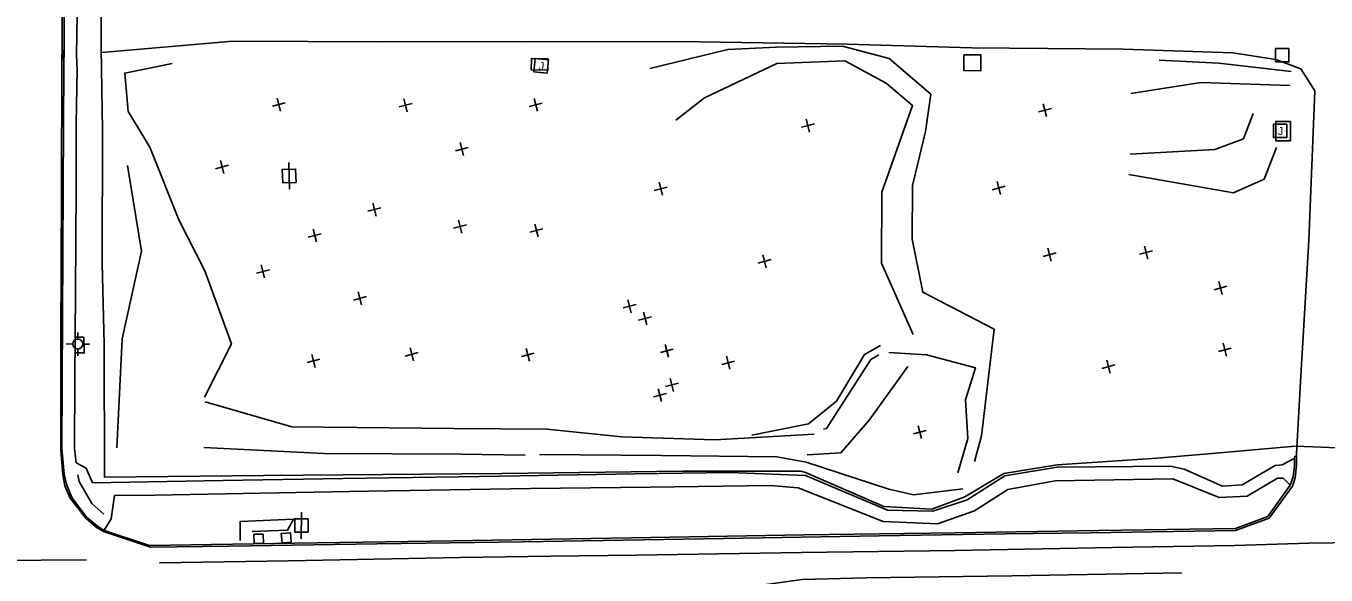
# Model space of a CAD drawing. Extents: x 4711259 to 4716401, y 890074 to 892728.
# Drawn here: x 4712099.3 to 4712586.5, y 891365.1 to 891570.9 of the extents above; entities that cross this region are included whole.
import ezdxf

# ---------------------------------------------------------------- set-up
doc = ezdxf.new("R2010")
doc.units = 0
for name, color, linetype in [('E_HY_STORM_Inlet', 7, 'Continuous'), ('E_RDWY_PHOTOG_Fence', 7, 'Continuous'), ('E_RDWY_ROAD_Curb', 7, 'Continuous'), ('E_RDWY_ROAD_EdgeAsph', 7, 'Continuous'), ('E_RDWY_ROAD_EdgeConc', 7, 'Continuous'), ('E_RDWY_ROAD_Fence', 7, 'Continuous'), ('E_RDWY_ROAD_Sidewalk', 7, 'Continuous'), ('E_RDWY_ROAD_Striping', 7, 'Continuous'), ('E_RDWY_ROAD_TBofCurb', 7, 'Continuous'), ('E_TERR_DTM_BrkLines', 7, 'Continuous'), ('E_TERR_DTM_RandomPt', 7, 'Continuous'), ('E_UTIL_COMM_General', 7, 'Continuous'), ('E_UTIL_ELEC_GENERAL', 7, 'Continuous'), ('E_UTIL_ELEC_POLE', 7, 'Continuous'), ('E_UTIL_WTR_General', 7, 'Continuous')]:
    doc.layers.add(name, color=color, linetype=linetype)

msp = doc.modelspace()

# ---------------------------------------------------------------- linework, layer by layer
at = {"layer": 'E_HY_STORM_Inlet'}
msp.add_line((4712570.08, 891559.94), (4712570.08, 891559.94), dxfattribs=at)
msp.add_lwpolyline([(4712572.6, 891562.42), (4712572.56, 891557.42), (4712567.56, 891557.46), (4712567.6, 891562.46)], close=True, dxfattribs=at)
at = {"layer": 'E_RDWY_PHOTOG_Fence'}
for points in [[(4712574.97, 891413.38), (4712548.05, 891411.03), (4712523.15, 891408.85)], [(4712597.22, 891412.51), (4712575.15, 891413.33)], [(4712389.68, 891403.96), (4712391.41, 891403.56), (4712420.78, 891390.76), (4712438.69, 891389.77), (4712451.16, 891394.32), (4712465.69, 891403.09), (4712485.68, 891406.34), (4712523.15, 891408.85)], [(4712389.68, 891403.96), (4712345.41, 891403.96), (4712277.64, 891403.09)]]:
    msp.add_lwpolyline(points, dxfattribs=at)
at = {"layer": 'E_RDWY_ROAD_Curb'}
for points in [[(4712128.26, 891381.39), (4712125.55, 891383.03), (4712121.64, 891386.33), (4712115.83, 891393.82), (4712113.87, 891398.54), (4712113.04, 891402.77), (4712112.33, 891411.88), (4712112.37, 891453.3), (4712112.58, 891509.08), (4712112.73, 891556.54), (4712112.81, 891563.66), (4712113, 891591.26), (4712112.87, 891594.89), (4712113.25, 891611.03), (4712113.37, 891640.66), (4712113.52, 891682.17), (4712113.29, 891731.86), (4712112.03, 891796.52), (4712110.46, 891860.01), (4712109.29, 891889.41), (4712108.95, 891893.59), (4712107.64, 891922.46)], [(4712575.38, 891410.55), (4712575.36, 891406.08), (4712574.89, 891401.56), (4712573.93, 891398.33), (4712565.14, 891386.35), (4712552.59, 891381.81), (4712498.06, 891380.95), (4712466.16, 891380.48), (4712418.96, 891379.75), (4712360.71, 891378.82), (4712285.61, 891377.51)], [(4712145.91, 891375.46), (4712128.26, 891381.39)], [(4712285.61, 891377.51), (4712230.79, 891376.79), (4712175.47, 891375.85), (4712145.91, 891375.46)]]:
    msp.add_lwpolyline(points, dxfattribs=at)
at = {"layer": 'E_RDWY_ROAD_EdgeAsph'}
for points in [[(4712286.19, 891565.02), (4712233.05, 891564.94), (4712176.76, 891565.2), (4712127.72, 891560.88)], [(4712286.19, 891565.02), (4712351.62, 891564.91), (4712406.96, 891564.03), (4712453.7, 891562.63), (4712510.49, 891562.11), (4712551.53, 891560.76), (4712567.71, 891558.31), (4712577.04, 891554.83), (4712582.3, 891546.57)], [(4712582.3, 891546.57), (4712579.98, 891490.4), (4712576.93, 891437.62), (4712575.38, 891410.55)]]:
    msp.add_lwpolyline(points, dxfattribs=at)
at = {"layer": 'E_RDWY_ROAD_EdgeConc'}
for points in [[(4712288.57, 891554.45), (4712288.71, 891558.7), (4712294.97, 891558.51), (4712294.84, 891554.26)], [(4712450.79, 891560.05), (4712457.14, 891560.04), (4712457.12, 891554.11), (4712450.77, 891554.12)], [(4712573.14, 891535.11), (4712573.15, 891527.86), (4712567.65, 891527.85), (4712567.63, 891535.1)]]:
    msp.add_lwpolyline(points, close=True, dxfattribs=at)
msp.add_lwpolyline([(4712118.08, 891448.31), (4712121.08, 891448.31), (4712120.93, 891454.19), (4712117.99, 891454.18)], dxfattribs=at)
at = {"layer": 'E_RDWY_ROAD_Fence'}
for points in [[(4712128.59, 891451.64), (4712127.77, 891481.95), (4712127.92, 891531.97), (4712127.41, 891562.39), (4712127.6, 891590.09), (4712127.3, 891649.86), (4712127.17, 891700.22), (4712128.2, 891710.35), (4712134.44, 891739.35), (4712132.91, 891765.97), (4712132.02, 891783.01), (4712129.51, 891829.8), (4712126.66, 891879.73), (4712124.56, 891919.3), (4712121.22, 891968.8), (4712118.38, 892019.02), (4712115.97, 892060.36), (4712113.52, 892109.62), (4712110.82, 892170.44), (4712108.89, 892208.75)], [(4712277.64, 891403.09), (4712188.43, 891402.32), (4712128.73, 891401.7), (4712128.59, 891451.64)]]:
    msp.add_lwpolyline(points, dxfattribs=at)
at = {"layer": 'E_RDWY_ROAD_Sidewalk'}
for points in [[(4712118.88, 891695.33), (4712118.95, 891660.37), (4712118.95, 891642.42), (4712123.96, 891628.2), (4712124.58, 891622.91), (4712123, 891617.48), (4712118.71, 891609.04), (4712118.53, 891594.89), (4712118.62, 891582.72), (4712118.2, 891560.08), (4712118.39, 891554.48), (4712118.03, 891534.35), (4712118.11, 891510.21), (4712117.8, 891471.09), (4712117.51, 891438.4), (4712117.47, 891412.49), (4712118.02, 891407.07)], [(4712118.02, 891407.07), (4712121.82, 891405.17), (4712124.23, 891399.67), (4712173.07, 891400.45), (4712218.17, 891401.25), (4712261.66, 891401.93), (4712284.19, 891402.25)], [(4712574.55, 891408.71), (4712570, 891406.34), (4712567.41, 891406.14), (4712555.06, 891398.93), (4712547.65, 891398.38), (4712533.37, 891404.8), (4712528.25, 891405.86), (4712485.78, 891405.47), (4712466.11, 891402.28), (4712451.99, 891393.22), (4712439.16, 891388.96), (4712422.12, 891389.43), (4712391.37, 891402.4), (4712363.15, 891403.48), (4712327.47, 891402.99), (4712284.19, 891402.25)], [(4712288.4, 891397.56), (4712220.44, 891396.41), (4712147.6, 891395.04), (4712132.46, 891394.86), (4712131.14, 891386.08), (4712128.62, 891381.88)], [(4712288.4, 891397.56), (4712333.35, 891397.98), (4712378.33, 891398.62), (4712388.68, 891397.76), (4712420.57, 891385.13), (4712440.82, 891384.21), (4712454.68, 891389.17), (4712467.23, 891397.19), (4712484.91, 891400.37), (4712529.06, 891401.07), (4712546.47, 891394.15), (4712556.93, 891394.63), (4712568.28, 891401.32), (4712570.38, 891401.35), (4712573.08, 891398.72)]]:
    msp.add_lwpolyline(points, dxfattribs=at)
at = {"layer": 'E_RDWY_ROAD_Striping'}
for points in [[(4712295.9, 891372.09), (4712327.97, 891372.54), (4712389.88, 891373.54), (4712447.54, 891374.26), (4712506.48, 891375.36), (4712552.23, 891376.18)], [(4712149.24, 891369.63), (4712197.62, 891370.43), (4712261.95, 891371.65), (4712295.9, 891372.09)], [(4712532.41, 891365.94), (4712468.79, 891364.75), (4712414.14, 891363.99), (4712390.14, 891363.4), (4712331.95, 891355.22), (4712274.12, 891347.88)]]:
    msp.add_lwpolyline(points, dxfattribs=at)
at = {"layer": 'E_RDWY_ROAD_TBofCurb'}
for p, q in [((4712113.38, 891561.85), (4712113.3, 891558.37)), ((4712127.9, 891382.05), (4712128.45, 891381.7))]:
    msp.add_line(p, q, dxfattribs=at)
for points in [[(4712110.81, 891858.26), (4712112.23, 891806.23), (4712113.41, 891752.41), (4712113.86, 891699.59), (4712113.9, 891642.74), (4712113.8, 891609.38), (4712113.63, 891594.74), (4712113.61, 891591.26), (4712113.53, 891562.3), (4712113.49, 891555.88), (4712113.15, 891510.23), (4712112.99, 891461.79), (4712112.75, 891412.45), (4712113.54, 891402.88), (4712114.41, 891399.12), (4712116.39, 891394.09), (4712121.95, 891386.8), (4712125.93, 891383.52), (4712128.52, 891381.7)], [(4712573.08, 891398.72), (4712574.14, 891401.84), (4712574.64, 891405.96), (4712574.67, 891408.75), (4712574.74, 891409.73)], [(4712303.47, 891378.64), (4712333.6, 891379.1), (4712390.76, 891380.09), (4712447.34, 891380.94), (4712501.29, 891381.76), (4712552.54, 891382.54), (4712564.62, 891387.02), (4712573.08, 891398.72)], [(4712128.52, 891381.7), (4712145.55, 891376.08), (4712199.85, 891376.96), (4712259.32, 891377.91), (4712303.47, 891378.64)]]:
    msp.add_lwpolyline(points, dxfattribs=at)
at = {"layer": 'E_TERR_DTM_BrkLines'}
for points in [[(4712333.01, 891554.88), (4712362.25, 891562.05), (4712380.53, 891562.94), (4712405.27, 891563.24), (4712422.77, 891558.67), (4712438.37, 891545.25), (4712436.36, 891531.34), (4712431.55, 891511.02), (4712431.44, 891491.01), (4712435.33, 891471.08), (4712462.06, 891457.25)], [(4712431.79, 891455.28), (4712419.91, 891482.02), (4712419.99, 891508.61), (4712431.53, 891541.09), (4712421.68, 891549.37), (4712406.13, 891557.79), (4712380.64, 891556.74), (4712353.52, 891543.87), (4712342.75, 891535.61)], [(4712573.46, 891553.74), (4712546.34, 891556.93), (4712523.89, 891558.04)], [(4712166.17, 891431.71), (4712176.25, 891451.69), (4712166.23, 891479.12), (4712156.54, 891498.2), (4712145.72, 891525.46), (4712137.58, 891538.79), (4712136.26, 891553.2), (4712154.06, 891556.82)], [(4712573, 891548.55), (4712539.5, 891549.65), (4712513.29, 891545.59)], [(4712513.13, 891522.8), (4712544.76, 891524.52), (4712555.57, 891528.6), (4712559.14, 891538.01)], [(4712567.94, 891525.31), (4712563.32, 891513.45), (4712551.77, 891508.32), (4712512.56, 891515.21)], [(4712137.3, 891518.58), (4712142.6, 891486.5), (4712135.37, 891453.57), (4712133.37, 891412.72)], [(4712462.06, 891457.25), (4712457.32, 891417.28), (4712454.69, 891407.6)], [(4712419.57, 891451.12), (4712413.54, 891447.7), (4712403.05, 891430.22), (4712392.5, 891421.74), (4712371.27, 891417.47)], [(4712398.19, 891419.79), (4712399.22, 891419.97), (4712415.9, 891445.86), (4712418.87, 891447.64)], [(4712448.51, 891403.35), (4712452.2, 891416.24), (4712451.32, 891430.71), (4712455.07, 891442.68), (4712436.69, 891447.6), (4712422.6, 891448.5)], [(4712429.74, 891443.26), (4712415.32, 891423.07), (4712404.67, 891410.88), (4712392.04, 891410.07)], [(4712166.45, 891430.02), (4712198.84, 891420.63), (4712259.73, 891419.99), (4712294.42, 891419.72)], [(4712394.65, 891417.9), (4712357.45, 891415.72), (4712322.57, 891416.91), (4712294.42, 891419.72)], [(4712286.36, 891410.06), (4712262.19, 891410.35), (4712210.84, 891410.58), (4712165.97, 891412.84)], [(4712291.72, 891410.29), (4712337.62, 891409.91), (4712380.66, 891409.34), (4712391.61, 891407.38), (4712422.69, 891397.25), (4712431.91, 891395.12), (4712450.35, 891397.39)], [(4712128.48, 891387.86), (4712123.89, 891391.9), (4712119.18, 891400.09), (4712118.67, 891402.67)], [(4712183.99, 891381.33), (4712197.27, 891381.89), (4712199.49, 891386.02), (4712179.56, 891385.18), (4712179.52, 891378.04)], [(4712552.23, 891376.18), (4712580.09, 891377.04), (4712607.13, 891377.36)], [(4712121.93, 891370.82), (4712087.68, 891370.5), (4712051.57, 891366.65)]]:
    msp.add_lwpolyline(points, dxfattribs=at)
at = {"layer": 'E_TERR_DTM_RandomPt'}
for p, q in [((4712194.65, 891538.98), (4712193.38, 891543.82)), ((4712242.16, 891538.74), (4712240.89, 891543.58)), ((4712290.95, 891538.88), (4712289.68, 891543.72)), ((4712191.6, 891540.77), (4712196.43, 891542.04)), ((4712239.11, 891540.52), (4712243.94, 891541.79)), ((4712287.89, 891540.67), (4712292.73, 891541.94)), ((4712478.71, 891538.66), (4712483.54, 891539.93)), ((4712481.76, 891536.87), (4712480.49, 891541.71)), ((4712389.89, 891532.88), (4712394.73, 891534.15)), ((4712392.95, 891531.09), (4712391.68, 891535.93)), ((4712260.2, 891524.07), (4712265.03, 891525.36)), ((4712263.26, 891522.3), (4712261.97, 891527.13)), ((4712173.4, 891515.58), (4712172.13, 891520.42)), ((4712170.34, 891517.36), (4712175.18, 891518.64)), ((4712334.72, 891509.2), (4712339.55, 891510.47)), ((4712337.77, 891507.42), (4712336.5, 891512.26)), ((4712461.4, 891509.5), (4712466.24, 891510.78)), ((4712464.46, 891507.72), (4712463.19, 891512.56)), ((4712230.48, 891499.62), (4712229.19, 891504.45)), ((4712227.42, 891501.39), (4712232.25, 891502.68)), ((4712208.12, 891489.91), (4712206.84, 891494.75)), ((4712259.53, 891495.04), (4712264.37, 891496.31)), ((4712262.59, 891493.26), (4712261.32, 891498.09)), ((4712288.12, 891493.55), (4712292.96, 891494.82)), ((4712291.18, 891491.77), (4712289.91, 891496.61)), ((4712205.06, 891491.7), (4712209.9, 891492.97)), ((4712376.71, 891480.22), (4712375.44, 891485.06)), ((4712480.46, 891484.52), (4712485.29, 891485.79)), ((4712483.51, 891482.73), (4712482.24, 891487.57)), ((4712516.62, 891485.31), (4712521.45, 891486.58)), ((4712519.67, 891483.52), (4712518.4, 891488.36)), ((4712188.71, 891476.46), (4712187.41, 891481.29)), ((4712373.66, 891482.01), (4712378.49, 891483.28)), ((4712185.65, 891478.23), (4712190.48, 891479.52)), ((4712547.56, 891470.22), (4712546.29, 891475.06)), ((4712225.06, 891466.38), (4712223.76, 891471.21)), ((4712544.51, 891472.01), (4712549.35, 891473.28)), ((4712221.99, 891468.15), (4712226.82, 891469.45)), ((4712323.05, 891465.19), (4712327.89, 891466.46)), ((4712326.11, 891463.4), (4712324.83, 891468.24)), ((4712328.86, 891460.57), (4712333.69, 891461.84)), ((4712331.91, 891458.79), (4712330.64, 891463.63)), ((4712340.07, 891446.67), (4712338.8, 891451.51)), ((4712549.18, 891447.1), (4712547.91, 891451.94)), ((4712204.59, 891444.69), (4712209.42, 891445.96)), ((4712207.64, 891442.91), (4712206.37, 891447.74)), ((4712241.41, 891447.16), (4712246.25, 891448.43)), ((4712244.47, 891445.38), (4712243.2, 891450.21)), ((4712284.92, 891446.95), (4712289.75, 891448.22)), ((4712287.97, 891445.17), (4712286.7, 891450.01)), ((4712337.02, 891448.45), (4712341.86, 891449.72)), ((4712363.07, 891442.22), (4712361.8, 891447.06)), ((4712546.13, 891448.88), (4712550.96, 891450.16)), ((4712360.01, 891444), (4712364.85, 891445.28)), ((4712502.51, 891442.53), (4712507.35, 891443.8)), ((4712505.56, 891440.75), (4712504.29, 891445.59)), ((4712338.92, 891435.7), (4712343.76, 891436.97)), ((4712341.98, 891433.92), (4712340.7, 891438.75)), ((4712334.43, 891431.86), (4712339.26, 891433.13)), ((4712337.48, 891430.08), (4712336.21, 891434.92)), ((4712431.83, 891417.97), (4712436.67, 891419.24)), ((4712434.88, 891416.19), (4712433.61, 891421.03))]:
    msp.add_line(p, q, dxfattribs=at)
at = {"layer": 'E_UTIL_COMM_General'}
for points in [[(4712188.19, 891380.42), (4712188.27, 891376.93), (4712184.77, 891376.85), (4712184.69, 891380.34)], [(4712195.22, 891377.1), (4712194.87, 891380.58), (4712198.36, 891380.93), (4712198.7, 891377.44)]]:
    msp.add_lwpolyline(points, close=True, dxfattribs=at)
at = {"layer": 'E_UTIL_ELEC_GENERAL'}
for points in [[(4712294.62, 891553.21), (4712289.64, 891553.63), (4712290.07, 891558.62), (4712295.05, 891558.19)], [(4712571.77, 891529.02), (4712566.77, 891529.05), (4712566.79, 891534.05), (4712571.79, 891534.02)]]:
    msp.add_lwpolyline(points, close=True, dxfattribs=at)
at = {"layer": 'E_UTIL_ELEC_POLE'}
for p, q in [((4712198.05, 891509.66), (4712197.72, 891519.65)), ((4712202.45, 891378.67), (4712202.5, 891388.67))]:
    msp.add_line(p, q, dxfattribs=at)
for points in [[(4712195.47, 891512.07), (4712195.3, 891517.07), (4712200.3, 891517.24), (4712200.47, 891512.24)], [(4712199.97, 891381.18), (4712199.99, 891386.18), (4712204.99, 891386.15), (4712204.97, 891381.15)]]:
    msp.add_lwpolyline(points, close=True, dxfattribs=at)
at = {"layer": 'E_UTIL_WTR_General'}
for p, q in [((4712118.67, 891453.52), (4712118.68, 891456.02)), ((4712116.78, 891451.66), (4712114.28, 891451.67)), ((4712120.53, 891451.64), (4712123.03, 891451.63)), ((4712118.65, 891449.77), (4712118.64, 891447.27))]:
    msp.add_line(p, q, dxfattribs=at)
msp.add_circle((4712118.66, 891451.65), 1.87, dxfattribs=at)

# ---------------------------------------------------------------- texts
at = {"layer": 'E_UTIL_ELEC_GENERAL'}
for rotation, p in [(355.0771, (4712291.37, 891554.42)), (359.7251, (4712568.42, 891529.97))]:
    msp.add_text('J', height=3, rotation=rotation, dxfattribs=at).set_placement(p)

doc.saveas('drawing.dxf')
